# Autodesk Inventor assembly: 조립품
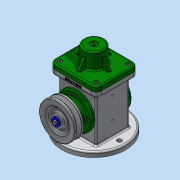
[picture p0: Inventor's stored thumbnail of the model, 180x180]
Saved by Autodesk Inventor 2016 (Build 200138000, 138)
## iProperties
Created: 2018-10
Part Number: 조립품
Material: 일반
Document SubType Name: Assembly
Designer: Administrator
Author: Administrator
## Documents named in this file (18)
- C:\Users\Administrator\Desktop\481007V1022\조립품.iam
- C:\Users\Administrator\Desktop\481007V1022\본체.ipt
- C:\Users\Administrator\Desktop\481007V1022\편심축.ipt
- C:\Users\Administrator\Desktop\481007V1022\베어링 17 x 40 x 12.ipt
- C:\Users\Administrator\Desktop\481007V1022\앞커버.ipt
- C:\Users\Administrator\Desktop\481007V1022\오일 실 17 30 8.ipt
- C:\Users\Administrator\Desktop\481007V1022\키 4 x 4 x 12.ipt
- C:\Users\Administrator\Desktop\481007V1022\V-벨트풀리.ipt
- C:\Users\Administrator\Desktop\481007V1022\와셔 4x16.ipt
- C:\Users\Administrator\Desktop\481007V1022\볼트 M4 x 10.ipt
- C:\Users\Administrator\Desktop\481007V1022\뒤커버.ipt
- C:\Users\Administrator\Desktop\481007V1022\볼트 M4 x 8.ipt
- C:\Users\Administrator\Desktop\481007V1022\슬라이더.ipt
- C:\Users\Administrator\Desktop\481007V1022\링크.ipt
- C:\Users\Administrator\Desktop\481007V1022\클레비스 핀 6 x 22.ipt
- 클레비스 핀 6 x 22.ipt
- C:\Users\Administrator\Desktop\481007V1022\E-링.ipt
- C:\Users\Administrator\Desktop\481007V1022\덮개.ipt
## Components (2 placed, 2 different names)
1. V-벨트풀리:1
2. E-링:1
